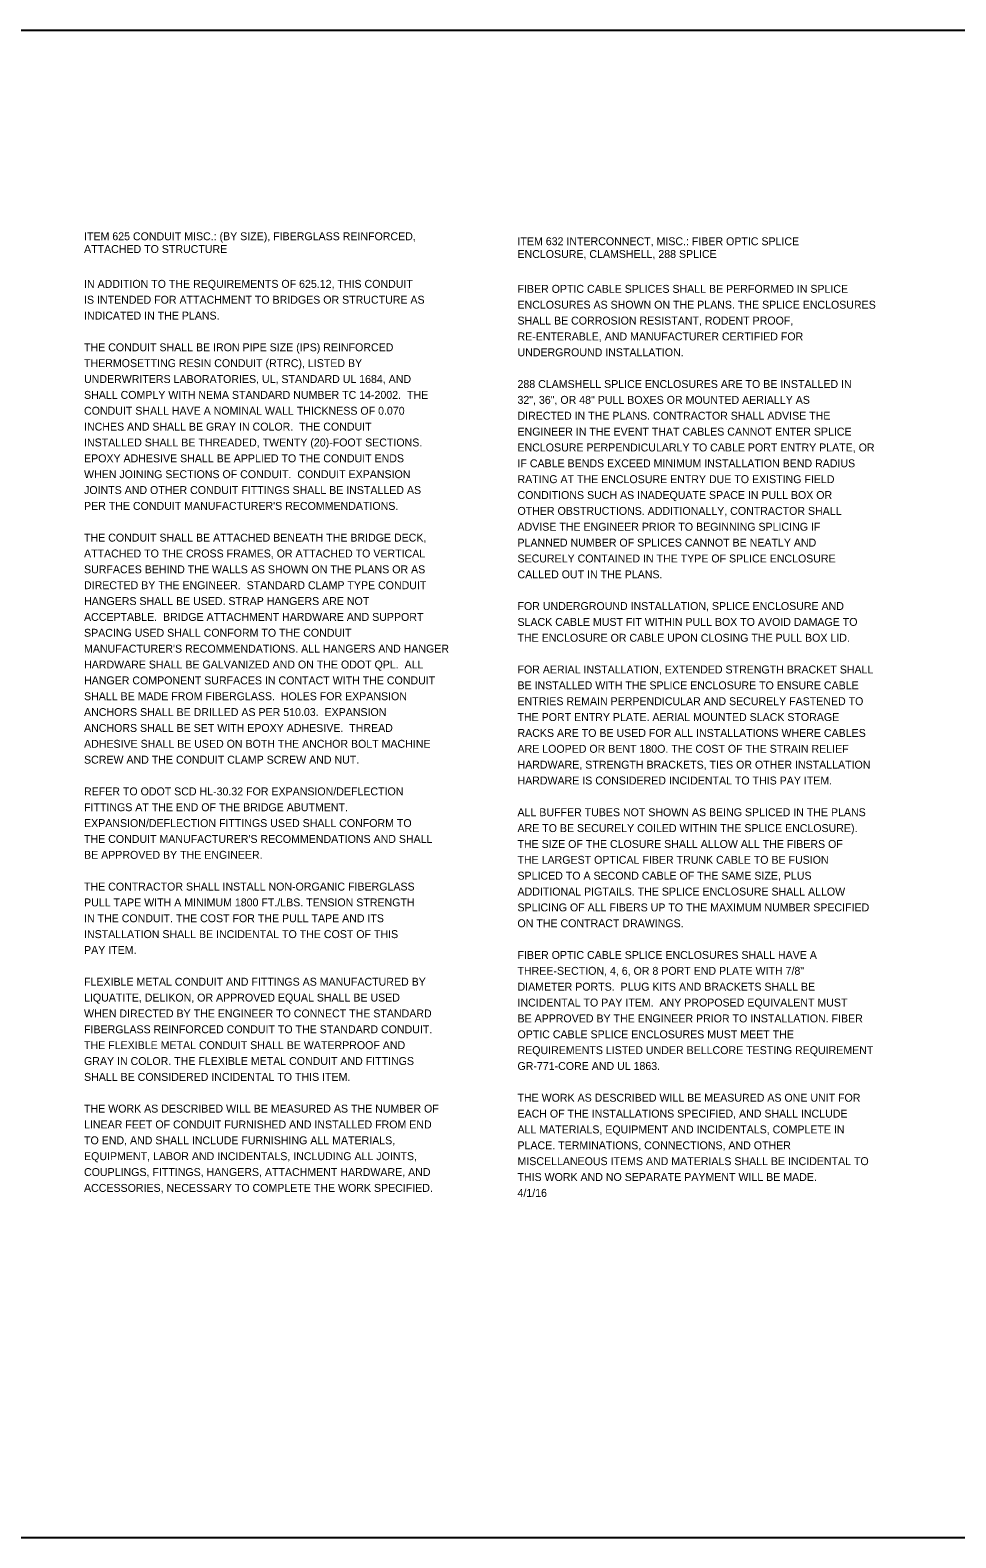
# Model space of a CAD drawing. Extents: x -41.3 to 53.7, y -40.1 to 14.5.
# Drawn here: x -18.45 to -2.11, y -40.09 to -13.47 of the extents above; entities that cross this region are included whole.
import ezdxf

# ---------------------------------------------------------------- set-up
doc = ezdxf.new("R2010")
doc.units = 0
doc.layers.add('SH_Data', color=7, linetype='Continuous')
doc.layers.add('SH_Text', color=7, linetype='Continuous')

msp = doc.modelspace()

# ---------------------------------------------------------------- linework, layer by layer
at = {"layer": 'SH_Text'}
msp.add_lwpolyline([(-41.349, -13.474), (32.055, -13.474), (32.055, -40.091), (-41.349, -40.091)], close=True, dxfattribs=at)

# ---------------------------------------------------------------- texts
at = {"layer": 'SH_Data'}
for s, p in [('ATTACHED TO STRUCTURE', (-17.499, -17.408)), ('ITEM 625 CONDUIT MISC.: (BY SIZE), FIBERGLASS REINFORCED, ', (-17.499, -17.183)), ('ITEM 632 INTERCONNECT, MISC.: FIBER OPTIC SPLICE ', (-9.847, -17.271)), ('ENCLOSURE, CLAMSHELL, 288 SPLICE', (-9.847, -17.496))]:
    msp.add_text(s, height=0.14, dxfattribs=at).set_placement(p)
at = {"layer": 'SH_Text'}
for s, p in [('IN ADDITION TO THE REQUIREMENTS OF 625.12, THIS CONDUIT ', (-17.499, -18.023)), ('FIBER OPTIC CABLE SPLICES SHALL BE PERFORMED IN SPLICE ', (-9.847, -18.111)), ('IS INTENDED FOR ATTACHMENT TO BRIDGES OR STRUCTURE AS ', (-17.499, -18.303)), ('ENCLOSURES AS SHOWN ON THE PLANS. THE SPLICE ENCLOSURES ', (-9.847, -18.391)), ('INDICATED IN THE PLANS.', (-17.499, -18.583)), ('SHALL BE CORROSION RESISTANT, RODENT PROOF, ', (-9.847, -18.671)), ('RE-ENTERABLE, AND MANUFACTURER CERTIFIED FOR ', (-9.847, -18.951)), ('THE CONDUIT SHALL BE IRON PIPE SIZE (IPS) REINFORCED ', (-17.499, -19.143)), ('UNDERGROUND INSTALLATION.', (-9.847, -19.231)), ('THERMOSETTING RESIN CONDUIT (RTRC), LISTED BY ', (-17.499, -19.423)), ('UNDERWRITERS LABORATORIES, UL, STANDARD UL 1684, AND ', (-17.499, -19.703)), ('288 CLAMSHELL SPLICE ENCLOSURES ARE TO BE INSTALLED IN ', (-9.847, -19.791)), ('SHALL COMPLY WITH NEMA STANDARD NUMBER TC 14-2002.  THE ', (-17.499, -19.983)), ('32", 36", OR 48" PULL BOXES OR MOUNTED AERIALLY AS ', (-9.847, -20.071)), ('CONDUIT SHALL HAVE A NOMINAL WALL THICKNESS OF 0.070 ', (-17.499, -20.263)), ('DIRECTED IN THE PLANS. CONTRACTOR SHALL ADVISE THE ', (-9.847, -20.351)), ('INCHES AND SHALL BE GRAY IN COLOR.  THE CONDUIT ', (-17.499, -20.543)), ('ENGINEER IN THE EVENT THAT CABLES CANNOT ENTER SPLICE ', (-9.847, -20.631)), ('INSTALLED SHALL BE THREADED, TWENTY (20)-FOOT SECTIONS.  ', (-17.499, -20.823)), ('EPOXY ADHESIVE SHALL BE APPLIED TO THE CONDUIT ENDS ', (-17.499, -21.103)), ('ENCLOSURE PERPENDICULARLY TO CABLE PORT ENTRY PLATE, OR ', (-9.847, -20.911)), ('WHEN JOINING SECTIONS OF CONDUIT.  CONDUIT EXPANSION ', (-17.499, -21.383)), ('IF CABLE BENDS EXCEED MINIMUM INSTALLATION BEND RADIUS ', (-9.847, -21.191)), ('JOINTS AND OTHER CONDUIT FITTINGS SHALL BE INSTALLED AS ', (-17.499, -21.663)), ('RATING AT THE ENCLOSURE ENTRY DUE TO EXISTING FIELD ', (-9.847, -21.471)), ("PER THE CONDUIT MANUFACTURER'S RECOMMENDATIONS.", (-17.499, -21.943)), ('CONDITIONS SUCH AS INADEQUATE SPACE IN PULL BOX OR ', (-9.847, -21.751)), ('OTHER OBSTRUCTIONS. ADDITIONALLY, CONTRACTOR SHALL ', (-9.847, -22.031)), ('ADVISE THE ENGINEER PRIOR TO BEGINNING SPLICING IF ', (-9.847, -22.311)), ('THE CONDUIT SHALL BE ATTACHED BENEATH THE BRIDGE DECK, ', (-17.499, -22.503)), ('PLANNED NUMBER OF SPLICES CANNOT BE NEATLY AND ', (-9.847, -22.591)), ('ATTACHED TO THE CROSS FRAMES, OR ATTACHED TO VERTICAL ', (-17.499, -22.783)), ('SECURELY CONTAINED IN THE TYPE OF SPLICE ENCLOSURE ', (-9.847, -22.871)), ('SURFACES BEHIND THE WALLS AS SHOWN ON THE PLANS OR AS ', (-17.499, -23.063)), ('CALLED OUT IN THE PLANS.', (-9.847, -23.151)), ('DIRECTED BY THE ENGINEER.  STANDARD CLAMP TYPE CONDUIT ', (-17.499, -23.343)), ('HANGERS SHALL BE USED. STRAP HANGERS ARE NOT ', (-17.499, -23.623)), ('FOR UNDERGROUND INSTALLATION, SPLICE ENCLOSURE AND ', (-9.847, -23.711)), ('ACCEPTABLE.  BRIDGE ATTACHMENT HARDWARE AND SUPPORT ', (-17.499, -23.903)), ('SLACK CABLE MUST FIT WITHIN PULL BOX TO AVOID DAMAGE TO ', (-9.847, -23.991)), ('SPACING USED SHALL CONFORM TO THE CONDUIT ', (-17.499, -24.183)), ('THE ENCLOSURE OR CABLE UPON CLOSING THE PULL BOX LID.', (-9.847, -24.271)), ("MANUFACTURER'S RECOMMENDATIONS. ALL HANGERS AND HANGER ", (-17.499, -24.463)), ('HARDWARE SHALL BE GALVANIZED AND ON THE ODOT QPL.  ALL ', (-17.499, -24.743)), ('FOR AERIAL INSTALLATION, EXTENDED STRENGTH BRACKET SHALL ', (-9.847, -24.831)), ('HANGER COMPONENT SURFACES IN CONTACT WITH THE CONDUIT ', (-17.499, -25.023)), ('BE INSTALLED WITH THE SPLICE ENCLOSURE TO ENSURE CABLE ', (-9.847, -25.111)), ('SHALL BE MADE FROM FIBERGLASS.  HOLES FOR EXPANSION ', (-17.499, -25.303)), ('ENTRIES REMAIN PERPENDICULAR AND SECURELY FASTENED TO ', (-9.847, -25.391)), ('ANCHORS SHALL BE DRILLED AS PER 510.03.  EXPANSION ', (-17.499, -25.583)), ('THE PORT ENTRY PLATE. AERIAL MOUNTED SLACK STORAGE ', (-9.847, -25.671)), ('ANCHORS SHALL BE SET WITH EPOXY ADHESIVE.  THREAD ', (-17.499, -25.863)), ('RACKS ARE TO BE USED FOR ALL INSTALLATIONS WHERE CABLES ', (-9.847, -25.951)), ('ADHESIVE SHALL BE USED ON BOTH THE ANCHOR BOLT MACHINE ', (-17.499, -26.143)), ('SCREW AND THE CONDUIT CLAMP SCREW AND NUT.', (-17.499, -26.423)), ('ARE LOOPED OR BENT 180O. THE COST OF THE STRAIN RELIEF ', (-9.847, -26.231)), ('HARDWARE, STRENGTH BRACKETS, TIES OR OTHER INSTALLATION ', (-9.847, -26.511)), ('REFER TO ODOT SCD HL-30.32 FOR EXPANSION/DEFLECTION ', (-17.499, -26.983)), ('HARDWARE IS CONSIDERED INCIDENTAL TO THIS PAY ITEM.', (-9.847, -26.791)), ('FITTINGS AT THE END OF THE BRIDGE ABUTMENT. ', (-17.499, -27.263)), ('EXPANSION/DEFLECTION FITTINGS USED SHALL CONFORM TO ', (-17.499, -27.543)), ('ALL BUFFER TUBES NOT SHOWN AS BEING SPLICED IN THE PLANS ', (-9.847, -27.351)), ("THE CONDUIT MANUFACTURER'S RECOMMENDATIONS AND SHALL ", (-17.499, -27.823)), ('ARE TO BE SECURELY COILED WITHIN THE SPLICE ENCLOSURE).  ', (-9.847, -27.631)), ('THE SIZE OF THE CLOSURE SHALL ALLOW ALL THE FIBERS OF ', (-9.847, -27.911)), ('BE APPROVED BY THE ENGINEER.', (-17.499, -28.103)), ('THE LARGEST OPTICAL FIBER TRUNK CABLE TO BE FUSION ', (-9.847, -28.191)), ('SPLICED TO A SECOND CABLE OF THE SAME SIZE, PLUS ', (-9.847, -28.471)), ('THE CONTRACTOR SHALL INSTALL NON-ORGANIC FIBERGLASS ', (-17.499, -28.663)), ('ADDITIONAL PIGTAILS. THE SPLICE ENCLOSURE SHALL ALLOW ', (-9.847, -28.751)), ('PULL TAPE WITH A MINIMUM 1800 FT./LBS. TENSION STRENGTH ', (-17.499, -28.943)), ('SPLICING OF ALL FIBERS UP TO THE MAXIMUM NUMBER SPECIFIED ', (-9.847, -29.031)), ('IN THE CONDUIT. THE COST FOR THE PULL TAPE AND ITS ', (-17.499, -29.223)), ('ON THE CONTRACT DRAWINGS.', (-9.847, -29.311)), ('INSTALLATION SHALL BE INCIDENTAL TO THE COST OF THIS ', (-17.499, -29.503)), ('PAY ITEM. ', (-17.499, -29.783)), ('FIBER OPTIC CABLE SPLICE ENCLOSURES SHALL HAVE A ', (-9.847, -29.871)), ('THREE-SECTION, 4, 6, OR 8 PORT END PLATE WITH 7/8" ', (-9.847, -30.151)), ('FLEXIBLE METAL CONDUIT AND FITTINGS AS MANUFACTURED BY ', (-17.499, -30.343)), ('DIAMETER PORTS.  PLUG KITS AND BRACKETS SHALL BE ', (-9.847, -30.431)), ('LIQUATITE, DELIKON, OR APPROVED EQUAL SHALL BE USED ', (-17.499, -30.623)), ('INCIDENTAL TO PAY ITEM.  ANY PROPOSED EQUIVALENT MUST ', (-9.847, -30.711)), ('WHEN DIRECTED BY THE ENGINEER TO CONNECT THE STANDARD ', (-17.499, -30.903)), ('BE APPROVED BY THE ENGINEER PRIOR TO INSTALLATION. FIBER ', (-9.847, -30.991)), ('FIBERGLASS REINFORCED CONDUIT TO THE STANDARD CONDUIT. ', (-17.499, -31.183)), ('OPTIC CABLE SPLICE ENCLOSURES MUST MEET THE ', (-9.847, -31.271)), ('THE FLEXIBLE METAL CONDUIT SHALL BE WATERPROOF AND ', (-17.499, -31.463)), ('GRAY IN COLOR. THE FLEXIBLE METAL CONDUIT AND FITTINGS ', (-17.499, -31.743)), ('REQUIREMENTS LISTED UNDER BELLCORE TESTING REQUIREMENT ', (-9.847, -31.551)), ('SHALL BE CONSIDERED INCIDENTAL TO THIS ITEM.', (-17.499, -32.023)), ('GR-771-CORE AND UL 1863.', (-9.847, -31.831)), ('THE WORK AS DESCRIBED WILL BE MEASURED AS THE NUMBER OF ', (-17.499, -32.583)), ('THE WORK AS DESCRIBED WILL BE MEASURED AS ONE UNIT FOR ', (-9.847, -32.391)), ('LINEAR FEET OF CONDUIT FURNISHED AND INSTALLED FROM END ', (-17.499, -32.863)), ('EACH OF THE INSTALLATIONS SPECIFIED, AND SHALL INCLUDE ', (-9.847, -32.671)), ('TO END, AND SHALL INCLUDE FURNISHING ALL MATERIALS, ', (-17.499, -33.143)), ('ALL MATERIALS, EQUIPMENT AND INCIDENTALS, COMPLETE IN ', (-9.847, -32.951)), ('PLACE. TERMINATIONS, CONNECTIONS, AND OTHER ', (-9.847, -33.231)), ('EQUIPMENT, LABOR AND INCIDENTALS, INCLUDING ALL JOINTS, ', (-17.499, -33.423)), ('MISCELLANEOUS ITEMS AND MATERIALS SHALL BE INCIDENTAL TO ', (-9.847, -33.511)), ('COUPLINGS, FITTINGS, HANGERS, ATTACHMENT HARDWARE, AND ', (-17.499, -33.703)), ('THIS WORK AND NO SEPARATE PAYMENT WILL BE MADE.', (-9.847, -33.791)), ('ACCESSORIES, NECESSARY TO COMPLETE THE WORK SPECIFIED.', (-17.499, -33.983)), ('4/1/16', (-9.847, -34.071))]:
    msp.add_text(s, height=0.14, dxfattribs=at).set_placement(p)

doc.saveas('drawing.dxf')
